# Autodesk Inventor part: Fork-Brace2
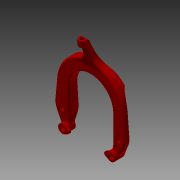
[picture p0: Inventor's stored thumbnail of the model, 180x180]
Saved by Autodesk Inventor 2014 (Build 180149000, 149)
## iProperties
Shininess: 64.0
Length Units: 11272
Angle Units: 11279
Time Units: 11290
Mass Units: 11286
Length Display Precision: 3
Angle Display Precision: 2
Compacted: True
Part Number: Fork-Brace2
Document SubType Name: Modeling
Created: 2003-10
Designer: Autodesk, Inc.
Manufacturer: Standard
Standards Organization: Custom
Mass: 76.1205 g
Surface Area: 223.813 cm^2
Volume: 76.1205 cm^3
Density: 1 g/cm^3
Material: Generic
Appearance: Red (Flat)_1
Density: 0.0
Volumn: 0.0
Area: 0.0
PropertySet Name: Model Information
Control State: 0
Master: False
Checked Out: False
Translation Standard: STEP AP214DIS
File Name: D:\\Documents and Settings\\garding\\My Documents\\My Work\\My Models\\Specialized M4\\Fork\\BRACE.stp
Preprocessor: Autodesk Inventor 8 Pre-Release
Postprocessor: Build: 057b, Release: 8 Pre-Release - Date: Sun 09/16/2003
Sent Units: INCHES
Uncertainty: 1.0000000000000002e-06
Author: Autodesk, Inc.
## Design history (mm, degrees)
feature "Base1"
sketch "Sketch1"
  geometry: L1 (-40.83, 0)-(-40.83, -45.941); L2 (38.288, -53.783)-(39.968, -52.909) reference; L3 (55.902, -40.649)-(48.019, -56.676) reference; L4 (54.945, 5.098)-(58.089, -28.786) reference; L5 (-27.85, 47.638)-(27.85, 47.638) reference; L6 (-58.09, -28.785)-(-54.945, 5.1) reference; L7 (-48.02, -56.678)-(-55.904, -40.648) reference; L8 (-39.968, -52.909)-(-38.288, -53.783) reference; L9 (-40.83, 0)-(-40.83, -45.941) reference; L10 (40.831, -45.941)-(40.831, 0) reference; C1 r 6.35 at (-48.578, -36.14); A1 r 7.302 centre (41.657, -60.261) between (48.019, -56.676) and (38.288, -53.783) reference; A2 r 22.225 centre (35.959, -30.839) between (55.902, -40.649) and (58.184, -30.839) reference; A3 r 22.225 centre (35.959, -30.839) between (58.184, -30.839) and (58.089, -28.786) reference; A4 r 55.181 centre (0, 0) between (54.945, 5.098) and (27.85, 47.638) reference; A5 r 55.182 centre (0, 0) between (-27.85, 47.638) and (-54.945, 5.1) reference; A6 r 22.225 centre (-35.961, -30.839) between (-58.09, -28.785) and (-58.186, -30.839) reference; A7 r 22.225 centre (-35.961, -30.839) between (-58.186, -30.839) and (-55.904, -40.648) reference; A8 r 7.302 centre (-41.657, -60.261) between (-38.288, -53.783) and (-48.02, -56.678) reference; A9 r 28.575 centre (-12.255, -45.941) between (-40.83, -45.941) and (-39.968, -52.909) reference; A10 r 40.83 centre (0, 0) between (40.831, 0) and (-40.83, 0) reference; A11 r 28.575 centre (12.255, -45.941) between (39.968, -52.909) and (40.831, -45.941) reference
  constraints: 2 end point, 1 centre point
  dimensions: "d15" = 7.74707 distance from line of C1.centre L1
hole "Hole1" sketch "Sketch1" at (-48.578, -36.14) diameter "d0" = 3.2512; stored, may be unused: countersink angle "d4" = 90 deg, drill point angle "d6" = 118 deg; dims "d1" = 12.7, "d2" = 7.62, "d3" = 6.35, "d5" = 19.05
workplane "Work Plane1"
sketch "Sketch2"
  geometry: C1 r 3.81 at (-89.044, -0.261) reference
hole "Hole2" sketch "Sketch2" at (-89.044, -0.261) diameter "d7" = 12.7; stored, may be unused: countersink angle "d11" = 0.1 deg, drill point angle "d13" = 0 deg; dims "d8" = 12.7, "d9" = 9.525, "d10" = 6.35, "d12" = 12.7
workaxis "Work Axis1"
workplane "Work Plane2"
mirror "Mirror1"
body "Solid1"
other parameters: "d14" = 0
